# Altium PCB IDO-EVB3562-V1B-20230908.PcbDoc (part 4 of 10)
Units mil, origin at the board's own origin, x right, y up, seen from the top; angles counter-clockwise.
Board outline 5314.96 x 3543.31 mil, 4 copper layers (TOP, L2-VCC, L3-GND, BOTTOM), stack 28.8 mil thick; 747 components, 560 nets, 2514 pads, 1964 vias.
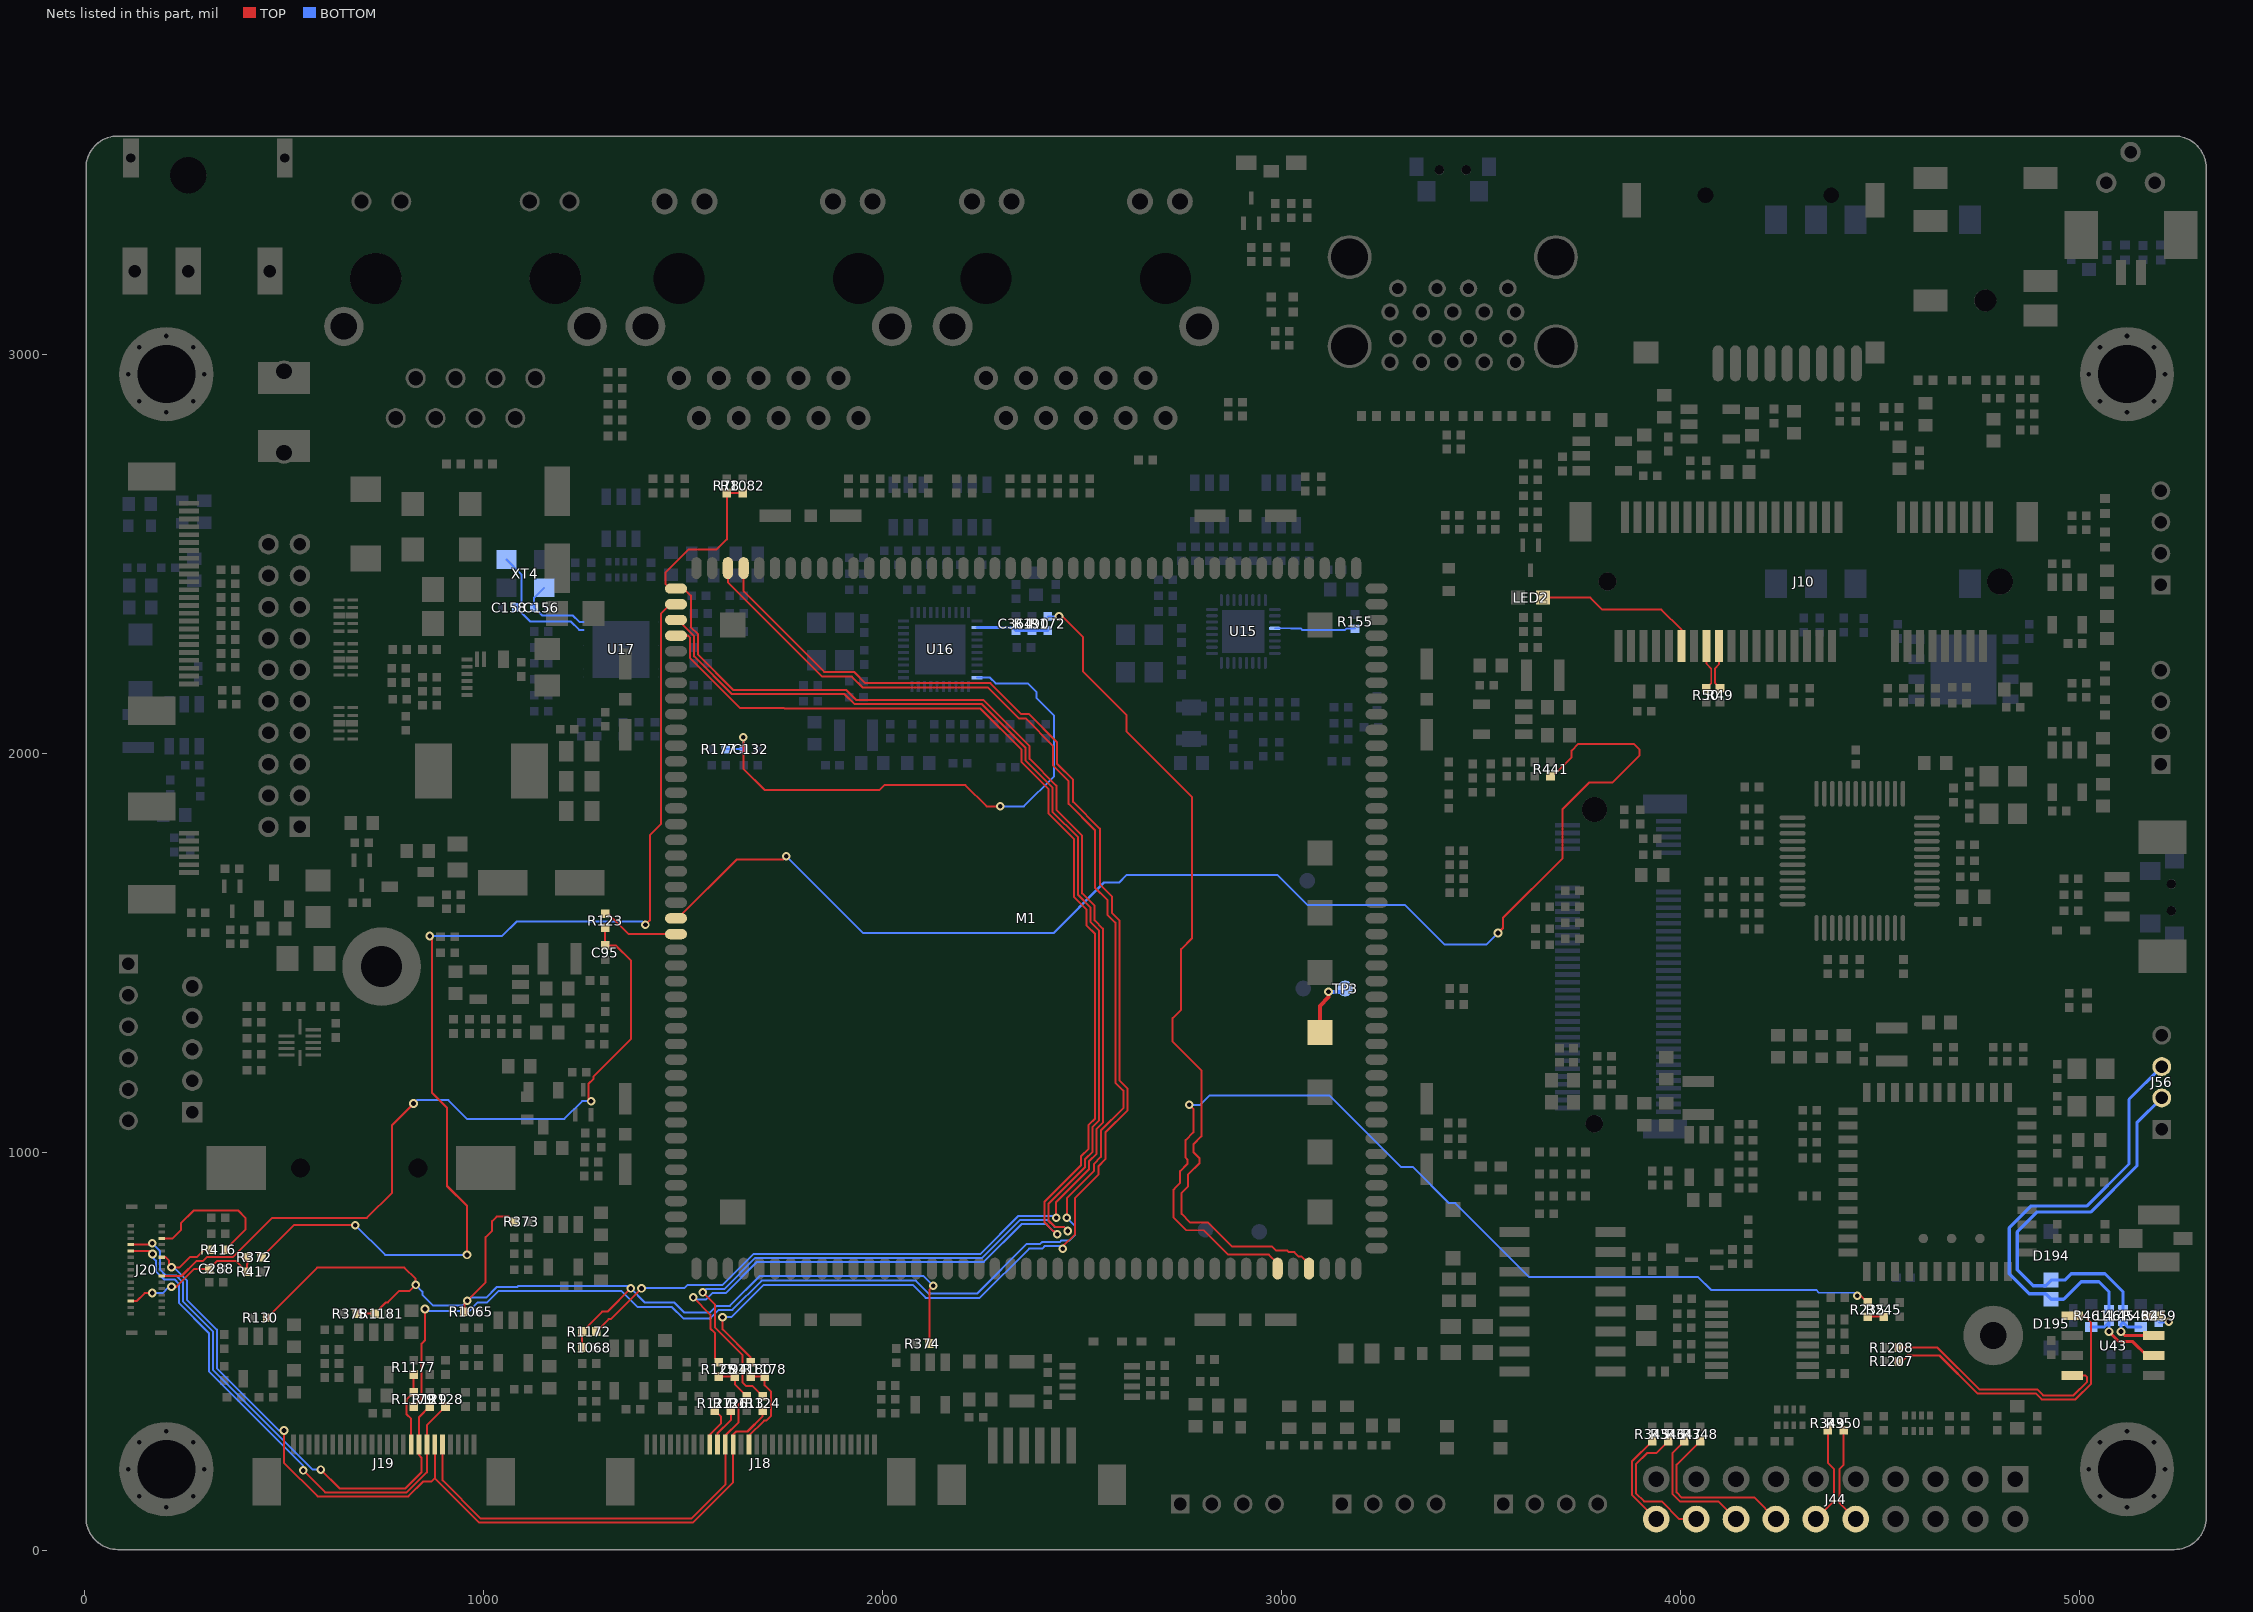
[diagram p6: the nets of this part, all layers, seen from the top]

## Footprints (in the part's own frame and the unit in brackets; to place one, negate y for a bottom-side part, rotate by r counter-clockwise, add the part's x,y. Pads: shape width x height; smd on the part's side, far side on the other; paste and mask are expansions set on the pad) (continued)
SILKSCREEN_TOP#14 [mm] "SILKSCREEN_TOP"
  rect 1.1x0.6 smd: 1(-1.35,0.95) 2(-1.35,0) 3(-1.35,-0.95) 4(1.35,-0.95) 5(1.35,0.95)
  silkscreen extent -2.03,-1.45 0.48,1.78, body extent -2.15,-1.8 2.15,1.65, height 3.81
SILKSCREEN_TOP#15 [mm] "SILKSCREEN_TOP"
  oct 0.025x0.025 smd: 1(-1.1,0.5) 2(0,-0.3) 3(-1.3,-1.1)
  rect 1.1x0.7 smd: 4(1.15,-1.02)
  rect 1x0.254 smd: 5(1.15,0.225) 6(1.15,0.675)
  rect 0.25x0.7 smd: 7(1.125,1.3) 8(0.675,1.3) 9(0.225,1.3) 10(-0.225,1.3) 11(-0.675,1.3) 12(-1.125,1.3)
  TOP region: 0.25,0.8 -1.55,0.8 -1.55,0.1 -0.8,0.1 -0.4,0.5 0.25,0.5 0.25,0.8
  TOP region: 0.25,0.8 -1.55,0.8 -1.55,0.1 -0.8,0.1 -0.4,0.5 0.25,0.5 0.25,0.8
  TOP region: 0.25,-1.4 -1.55,-1.4 -1.55,-0.7 -0.8,-0.7 -0.4,-1.1 0.25,-1.1 0.25,-1.4
  TOP region: 0.25,-1.4 -1.55,-1.4 -1.55,-0.7 -0.8,-0.7 -0.4,-1.1 0.25,-1.1 0.25,-1.4
  TOP region: -0.2,0.1 -0.5,-0.2 -0.5,-0.4 -0.2,-0.7 0.2,-0.7 0.5,-0.4 0.5,-0.2 0.2,0.1 -0.2,0.1
  TOP region: -0.2,0.1 -0.5,-0.2 -0.5,-0.4 -0.2,-0.7 0.2,-0.7 0.5,-0.4 0.5,-0.2 0.2,0.1 -0.2,0.1
  silkscreen extent -2.15,-1.5 1.5,1.5, body extent -1.55,-1.5 1.55,1.5, height 3.81
SILKSCREEN_TOP#16 [mm] "SILKSCREEN_TOP"
  rect 1.2x1.3 smd: 1(-0.9,1.2) 2(-0.9,-1.2) 3(0.9,-1.2) 4(0.9,1.2)
  silkscreen extent -1.92,-1.6 1.25,1.6, body extent -1.5,-1.85 1.5,1.85, height 3.81

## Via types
v1: diameter 21.65, hole 11.81, TOP to BOTTOM, 1964 vias

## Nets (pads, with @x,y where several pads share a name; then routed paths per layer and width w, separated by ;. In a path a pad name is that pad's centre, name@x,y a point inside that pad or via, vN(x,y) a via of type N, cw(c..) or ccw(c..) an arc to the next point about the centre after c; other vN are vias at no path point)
4G_DM: J10.36 R49.2 | length 115.2
  TOP w4.5: J10.36@4097.4,2268.6 4097.4,2222.67 4087.4,2212.67 4087.4,2175.32 R49.2@4100,2162.72
4G_DP: J10.38 R50.2 | length 116.2
  TOP w4.5: R50.2@4065,2162.72 4077.9,2175.62 4077.9,2212.1 4065.9,2224.1 J10.38@4065.9,2268.6
4G_LED_WANN#: J10.42 LED2.C | length 421
  TOP w5: LED2.C@3656.5,2390 3775,2390 3805,2360 3953,2360 4002.9,2310.1 J10.42@4002.9,2268.6
4G_POWER_H: M1.108 R441.1 | length 3262.6
  TOP w5: M1.108@1482.87,1585.83 1487.06,1585.83 1634.58,1733.35 1750.89,1733.35 v1(1759.22,1741.67) ; v1(3543.47,1549.33) 3555.81,1561.67 3555.81,1587.06 3704.43,1735.67 3704.43,1858.74 3772.69,1927 3830.75,1927 3897.61,1993.86 3897.61,2009.26 3883.54,2023.33 3744.95,2023.33 3728,2006.38 3728,1989.62 3680.66,1942.28 R441.1@3675,1942.28
  BOTTOM w5: v1(1759.22,1741.67) 1951.93,1548.96 2428.96,1548.96 2555.69,1675.69 2593.58,1675.69 2612.89,1695 2990,1695 3066,1619 3310.64,1619 3409.69,1519.94 3514.08,1519.94 v1(3543.47,1549.33)
ADC0: J44.10 R350.2 | length 243.8
  TOP w5: R350.2@4410,302.28 4410,216 4399,205 4399,121 J44.10@4440,80
ADC1: J44.12 R349.2 | length 247.1
  TOP w5: J44.12@4340,80 4385,125 4385,206 4370,221 R349.2@4370,302.28
ADC2: J44.14 R348.2 | length 429.7
  TOP w5: R348.2@4050,275.28 3990.97,216.25 3990.97,146.72 4004.14,133.54 4186.46,133.54 J44.14@4240,80
ADC3: J44.16 R347.2 | length 329.7
  TOP w5: R347.2@4010,275.28 3980.97,246.25 3980.97,142.57 4000,123.54 4096.46,123.54 J44.16@4140,80
ADC4: J44.18 R346.2 | length 355
  TOP w5: R346.2@3970,275.28 3939.72,245 3916.86,245 3889.03,217.17 3889.03,145.11 3909.57,124.57 3953.36,124.57 3997.93,80 J44.18@4040,80
ADC5: J44.20 R345.2 | length 241.6
  TOP w5: R345.2@3930,275.28 3879.03,224.31 3879.03,140.97 J44.20@3940,80
AF-PWDN: J20.26 R416.2 | length 356.8
  TOP w5: J20.26@193.98,783.74 220.66,783.74 241.33,804.41 241.33,821.33 273.5,853.5 384.83,853.5 403.33,835 403.33,805.61 R416.2@352.72,755
BATDIV: M1.176 TP3.1 | length 155.9
  TOP w10: M1.176@3096.65,1300 3096.65,1366.65 3118.29,1388.3 v1(3118.29,1401.8)
  BOTTOM w10: v1(3118.29,1401.8) 3151.8,1401.8 TP3.1@3160,1410
BT_REG_ON_H: R235.2 R245.1 | length 40
  TOP w5: R235.2@4470,587.28 R245.1@4510,587.28
BT_REG_ON_H_GPIO0_B0_D: M1.167 R235.1 | length 2559.2
  TOP w5: v1(2769,1118.59) 2779.55,1108.04 2779.55,1049.55 2760,1030 2760,985.86 2765,980.86 2765,970.71 2746.68,952.39 2746.68,922.67 2735.88,911.87 2730.03,906.02 2730.03,835.83 2761.86,804 2806,804 2867.07,742.93 2969.07,742.93 2990.75,721.25 M1.167@2990.75,707.87 ; v1(4444.12,640.12) 4452.6,640.12 R235.1@4470,622.72
  BOTTOM w5: v1(2769,1118.59) 2797.01,1118.59 2820.49,1142.07 3120.79,1142.07 3299.86,963 3329.58,963 3420.41,872.17 3436.58,872.17 3622.08,686.67 4044.91,686.67 4077.23,654.35 4340.65,654.35 4347.67,647.33 4436.91,647.33 v1(4444.12,640.12)
CAM_CLK0_OUT_M1: M1.109 R123.1 | length 199.2
  TOP w5: R123.1@1305,1597.72 1313.28,1597.72 1364.65,1546.35 1425.35,1546.35 1425.46,1546.46 M1.109@1482.87,1546.46
CAM_CLK2_OUT: M1.84 R1179.1 | length 4437
  TOP w5: R1179.1@825,362.28 845,382.28 845,520 853.53,528.53 v1(853.53,606.52) ; M1.84@1612.8,2463.78 1612.8,2428.2 1849,2192 1923.73,2192 1951.41,2164.33 2265.1,2164.33 2342.43,2087 2358.92,2087 2428.33,2017.59 2428.33,1993.59 ; 2428.32,1993.58 2428.32,1985.3 2428.32,1968.73 2467,1930.05 2467,1873 2533,1807 2533,1663 2564,1632 2564,1595 2584,1575 2584,1174 2604,1154 2604,1110 2548,1054 2548,988 2530,970 2530,952 2462.42,884.42 v1(2462.42,835)
  BOTTOM w5: v1(853.53,606.52) 859.05,601 964,601 986,623 1009,623 1037.5,651.5 1346.5,651.5 1386.66,611.34 1472.66,611.34 1501,583 1569,583 1590.33,604.33 1623.88,604.33 1697.45,677.9 2084.1,677.9 2116.7,645.3 2237.3,645.3 2361.7,769.7 2395.7,769.7 2400.58,774.58 2444.75,774.58 2448.17,778 2468,778 2483.17,793.17 2483.17,814.25 v1(2462.42,835)
CAM_CLK3_OUT: M1.83 R1180.1 | length 3509.9
  TOP w5: v1(1599.36,586) 1599.36,555.7 1670,485.06 R1180.1@1670,472.72 ; M1.83@1652.16,2463.78 1652.16,2405.84 1854,2204 1928.88,2204 1957.55,2175.33 2270.67,2175.33 2347.39,2098.61 2366.45,2098.61 2438.33,2026.74 2438.33,1989.44 ; 2438.32,1989.44 2438.32,1981.16 2438.32,1972.88 2478,1933.2 2478,1878 2545,1811 2545,1671 2576,1640 2576,1599 2594,1581 2594,1180 2615,1159 2615,1105 2559,1049 2559,982 2542,965 2542,944 2483.17,885.17 2483.17,794.43 2452.2,763.47 v1(2452.2,757.84)
  BOTTOM w5: v1(1599.36,586) 1621.69,586 1702.69,667 2076,667 2108.7,634.3 2244.04,634.3 2367.74,758 2401,758 2407.58,764.58 2445.46,764.58 v1(2452.2,757.84)
CAN0_H: D194.A J56.2 L45.2 | length 1015.5
  BOTTOM w8: L45.2@5110,606.93 5110,650 5065,695 4980,695 4963.98,678.98 D194.A@4930,678.98 4916.02,665 4885,665 4845,705 4845,800 4895,850 5030,850 5145,965 5145,1073.35 J56.2@5207.28,1135.63
CAN0_L: D195.A J56.3 L46.2 | length 1107.9
  BOTTOM w8: L46.2@5075,606.93 5075,650 5050,675 5005,675 4961.02,631.02 D195.A@4930,631.02 4916.02,645 4875,645 4825,695 4825,810 4880,865 5020,865 5125,970 5125,1132.09 J56.3@5207.28,1214.37
CAN0_RX_M2: R1208.2 U43.4 | length 586.5
  TOP w5: R1208.2@4547.72,510 4645,510 4750,405 4895,405 4910,390 4986,390 5020,424 5020,435 5015,440 U43.4@4982.64,440
CAN0_STB_IO: R459.1 U43.8 | length 70
  TOP w5: U43.8@5187.36,590 5210,590 v1(5225,575)
  BOTTOM w5: R459.1@5200,572.28 5222.28,572.28 v1(5225,575)
CAN0_TX_M2: R1207.2 U43.1 | length 758
  TOP w5: R1207.2@4547.72,475 4555,475 4570,490 4650,490 4745,395 4890.86,395 4905.86,380 4991,380 5030,419 5030,572 5012,590 U43.1@4982.64,590
CAN0H: L45.1 R462.1 U43.7 | length 161.5
  TOP w8: v1(5105,550) 5115,540 U43.7@5187.36,540
  BOTTOM w8: v1(5105,550) 5105,568.07 L45.1@5110,573.07 5121.61,561.46 R462.1@5155,561.46
CAN0L: L46.1 R461.1 U43.6 | length 210.1
  TOP w8: v1(5075,550) 5100,525 5135,525 5170,490 U43.6@5187.36,490
  BOTTOM w8: R461.1@5030,561.46 5063.39,561.46 L46.1@5075,573.07 v1(5075,550)
CIF1_SCL: J18.21 R126.2 | length 99.1
  TOP w5: J18.21@1586.73,267.01 1586.73,295 1620,328.27 R126.2@1620,352.28
CIF1_SDA: J18.22 R127.2 | length 103.1
  TOP w5: J18.22@1567.05,267.01 1567.05,291.05 1595,319 1595,337.28 R127.2@1580,352.28
CIF2_RST: C288.2 J20.5 R372.2 R417.1 | length 380.3
  TOP w5: J20.5@116.03,626.26 130.26,626.26 150.59,646.59 v1(169.9,646.59) ; v1(218.07,662.25) 230.25,662.25 275,707 C288.2@312.28,707 331.93,726.65 380.63,726.65 R417.1@407.28,700 407.28,719 408.28,720 R372.2@408.28,736
  BOTTOM w5: v1(169.9,646.59) 195.65,646.59 211.31,662.25 v1(218.07,662.25)
CIF2_RST_L: M1.88 R372.1 | length 2820.4
  TOP w5: R372.1@443.72,736 524.55,816.83 v1(678.75,816.83) ; v1(865.6,1541.78) 870.61,1536.77 870.61,1149.39 908.65,1111.35 908.65,915 958.75,864.9 v1(958.75,742.17) ; v1(1406,1569.67) 1417,1580.67 1417,1793.92 1445,1821.92 1445,2350 1468.23,2373.23 M1.88@1482.87,2373.23
  BOTTOM w5: v1(678.75,816.83) 753.4,742.17 v1(958.75,742.17) ; v1(865.6,1541.78) 1046.78,1541.78 1083,1578 1397.67,1578 v1(1406,1569.67)
CIF2_SCL: J19.7 J20.21 R128.2 | length 1310.1
  TOP w5: J20.21@116.03,752.24 162.61,752.24 v1(170.34,744.51) ; v1(548.02,202) 603.35,146.67 807.74,146.67 858.27,197.2 J19.7@858.27,267.01 858.27,315.55 R128.2@905,362.28
  BOTTOM w5: v1(170.34,744.51) 170.34,735.89 178.67,727.56 178.67,701.76 199.86,680.58 225.66,680.58 236.39,669.84 236.39,621.75 311.67,546.48 311.67,450.12 548.02,213.77 v1(548.02,202)
CIF2_SDA: J19.8 J20.23 R129.2 | length 1291.3
  TOP w5: J20.23@116.03,767.99 166.55,767.99 v1(169.72,771.15) ; v1(592,204) 639.33,156.67 803.59,156.67 844.77,197.85 844.77,234.23 838.58,240.42 J19.8@838.58,267.01 838.58,335.86 R129.2@865,362.28
  BOTTOM w5: v1(169.72,771.15) 188.67,752.2 188.67,705.9 204,690.58 229.8,690.58 246.39,673.98 246.39,625.9 321.67,550.62 321.67,454.26 571.94,204 v1(592,204)
CIF_EN: R130.1 R373.1 R374.1 R375.1 R1065.1 R1068.1 R1172.2 R1181.1 | length 2725.1
  TOP w5: R130.1@457.72,585 457.72,585.14 583.08,710.5 801.5,710.5 830,682 v1(830,667.02) 814.98,652 789,652 760.5,623.5 755.78,623.5 R1181.1@727.28,595 R375.1@682.72,595 ; R1065.1@952.28,600 952.28,619.77 v1(959.53,627.02) 1005.67,673.16 1005.67,786.53 1022,802.85 1022,827 1033,838 1064.28,838 R373.1@1077.28,825 ; R1068.1@1247.28,510 R1172.2@1247.28,550 1297.28,600 1310.98,600 v1(1369.15,658.17) ; R374.1@2117.72,520 2117.72,654.89 v1(2127.46,664.63)
  BOTTOM w5: v1(830,667.02) 846.67,650.35 846.67,642.41 874.08,615 947.51,615 v1(959.53,627.02) 967.86,635.35 1006.55,635.35 1032.71,661.5 1084.63,661.5 1087.13,664 1363.32,664 v1(1369.15,658.17) 1404.98,622.34 1479,622.34 1504.02,597.32 1567.32,597.32 1584.33,614.33 1617.73,614.33 1693.31,689.9 2102.18,689.9 v1(2127.46,664.63)
CIF_PDN: J18.19 J19.6 J20.20 R124.2 R416.1 | length 2355.5
  TOP w5: J20.20@193.98,736.49 203.51,736.49 212,728 212,717.1 v1(217.99,711.11) 238.64,711.11 264.02,736.49 281.49,736.49 300,755 R416.1@317.28,755 ; v1(499.93,301.93) 499.93,221.07 584.33,136.67 811.88,136.67 849.75,174.54 870,174.54 877.95,182.49 ; J19.6@877.95,267.01 877.95,182.49 ; R124.2@1700,352.28 1700,337.6 1661.91,299.51 1633.51,299.51 1626.1,292.1 J18.19@1626.1,267.01 1626.1,171.96 1525.15,71 989.44,71 877.95,182.49
  BOTTOM w5: v1(217.99,711.11) 223.41,711.11 256.39,678.13 256.39,630.04 331.67,554.76 331.67,458.41 488.15,301.93 v1(499.93,301.93)
CIF_PDN_L: M1.89 R124.1 | length 3744.4
  TOP w5: M1.89@1482.87,2333.86 1487.61,2333.86 1527.93,2293.53 1527.93,2242.53 1622.13,2148.33 1904.84,2148.33 1929.84,2123.33 2248.53,2123.33 2359,2012.86 2359,1981.48 2426,1914.48 2426,1853.46 2490.74,1788.71 2490.74,1644.48 2522.35,1612.88 2522.35,1576.65 2543,1556 2543,1079 2527,1063 2527,1001 2508,982 2508,962 2416.53,870.53 2416.53,828.47 2432.76,812.24 2454.62,812.24 v1(2464.84,802.02) ; v1(1549.83,648.17) 1580,618 1580,560.92 1650,490.92 1650,422 1659,413 1674.72,413 R124.1@1700,387.72
  BOTTOM w5: v1(1549.83,648.17) 1558.15,656.5 1603.33,656.5 1681.67,734.83 2250.3,734.83 2344.7,829.22 2415.28,829.22 2431.91,812.59 2454.27,812.59 v1(2464.84,802.02)
CIF_PWREN_H: M1.87 R78.2 R1082.2 R1172.1 | length 4112.4
  TOP w5: R1172.1@1282.72,550 1313.72,581 1319.17,581 v1(1396.35,658.17) ; R1082.2@1650,2652.28 R78.2@1610,2652.28 1610,2536 1584,2510 1513.75,2510 1456,2452.25 1456,2425 1468.4,2412.6 M1.87@1482.87,2412.6 1502.4,2412.6 1520,2395 1520,2315.61 1537.93,2297.68 1537.93,2246.67 1626.28,2158.33 1908.98,2158.33 1933.98,2133.33 2252.67,2133.33 2369,2017 2369,1985.62 2436,1918.62 2436,1857.6 2500.74,1792.86 2500.74,1648.63 2532.35,1617.02 2532.35,1580.8 2553,1560.14 2553,1074 2537,1058 2537,996 2518,977 2518,957 2435.76,874.76 v1(2435.76,835.15)
  BOTTOM w5: v1(1396.35,658.17) 1398.02,659.85 1504.35,659.85 1511,666.5 1599.19,666.5 1677.52,744.83 2246.16,744.83 2341.33,840 2430.92,840 v1(2435.76,835.15)
CIF_RST: C94.2 J18.20 J19.5 R113.1 R125.2 | length 1219.4
  TOP w5: J19.5@897.64,267.01 897.64,176.95 993.58,81 1521,81 1606.42,166.42 J18.20@1606.42,267.01 1606.42,289.42 1640,323 1640,367.72 R113.1@1660,387.72 1630.01,417.71 C94.2@1630.01,437.28 R125.2@1590,437.28
CIF_RST_L: M1.90 R125.1 | length 3564.8
  TOP w5: M1.90@1482.87,2294.49 1512.84,2294.49 1517.93,2289.39 1517.93,2238.38 1642.99,2113.33 1753.29,2113.33 1754.94,2111.67 2246.04,2111.67 2349,2008.71 2349,1977.34 2416,1910.34 2416,1849.32 2480.74,1784.57 2480.74,1639.26 2512.35,1607.65 2512.35,1567.65 2533,1547 2533,1084 2517,1068 2517,1008 2498,989 2498,967 2406.53,875.53 2406.53,823.83 2428.34,802.02 2430.06,802.02 v1(2438.17,793.91) ; v1(1526.03,635.65) 1569,592.68 1569,557.78 1580,546.78 1580,482.72 R125.1@1590,472.72
  BOTTOM w5: v1(1526.03,635.65) 1531.83,629.85 1557.42,629.85 1574.07,646.5 1607.48,646.5 1685.81,724.83 2254.45,724.83 2348.84,819.22 2411.14,819.22 2428.34,802.02 2430.06,802.02 v1(2438.17,793.91)
CKXTALIN: C156.1 U17.32 XT4.3 | length 198.1
  BOTTOM w5: XT4.3@1152.24,2414.57 1127.28,2389.6 C156.1@1127.28,2365 1147.28,2345 1224.34,2345 1240.39,2328.95 U17.32@1250.5,2328.95
CKXTALOUT: C158.2 U17.31 XT4.1 | length 331.8
  BOTTOM w5: XT4.1@1057.76,2485.43 1095,2448.19 1095,2377.28 C158.2@1082.72,2365 1117.72,2330 1219.34,2330 1240.09,2309.25 U17.31@1250.5,2309.25
CLKREQB: R155.2 U15.12 | length 204
  BOTTOM w4: U15.12@2983.74,2312.87 3024,2312.87
  BOTTOM w5: 3024,2312.87 3048.5,2312.87 3052.12,2309.25 3160.25,2309.25 3163.28,2312.28 R155.2@3185,2312.28
CSI0_MCLK: C95.2 J20.14 R123.2 | length 1920
  TOP w5: J20.14@193.98,689.25 243.11,689.25 280.35,726.49 296.49,726.49 306.65,736.65 371.65,736.65 470.15,835.15 707.84,835.15 771.02,898.34 771.02,1067.85 v1(824.84,1121.67) ; v1(1269.88,1127.62) 1263.41,1134.1 1263.41,1170.73 1276.07,1183.39 1276.07,1189.83 1370,1283.75 1370,1480 1332.28,1517.72 C95.2@1304.99,1517.72 ; C95.2@1304.99,1517.72 R123.2@1305,1562.28
  BOTTOM w5: v1(824.84,1121.67) 833.16,1130 911.86,1130 958.71,1083.14 1202.67,1083.14 1247.14,1127.62 v1(1269.88,1127.62)
CSI2_MCLK: J19.9 R1177.1 R1179.2 | length 187.9
  TOP w5: J19.9@818.9,267.01 818.9,331.1 806.65,343.35 806.65,379.37 R1179.2@825,397.72 R1177.1@825,442.28
CSI3_MCLK: J18.17 R1178.1 R1180.2 | length 238.3
  TOP w5: J18.17@1665.47,267.01 1665.47,288.93 1703.54,327 1709.42,327 1721,338.58 1721,399.03 1705,415.03 R1178.1@1705,437.28 R1180.2@1670,437.28
GMAC0_TXCLK_: C132.2 R177.2 U16.20 | length 1406.3
  TOP w5: v1(1651.52,2040) 1651.52,1960.91 1704.6,1907.83 1993.08,1907.83 2005.25,1920 2207.95,1920 2261.25,1866.7 v1(2295.26,1866.7)
  BOTTOM w5: R177.2@1607.72,2010 C132.2@1652.28,2010 1652.28,2039.24 v1(1651.52,2040) ; U16.20@2237.52,2189.13 2269.87,2189.13 2284,2175 2364.86,2175 2385.97,2153.89 2385.97,2138.56 2430.5,2094.03 2430.5,1942.5 2354.7,1866.7 v1(2295.26,1866.7)
GMAC1_RSTN: C364.2 R172.2 R190.1 U16.12 | length 180.7
  BOTTOM w8: U16.12@2237.52,2315.12 2327.16,2315.12 C364.2@2335,2307.28 R190.1@2375,2307.28 R172.2@2415,2307.28
GMAC1_RSTN_GPIO0_A6_D: M1.169 R172.1 | length 2134.9
  TOP w5: v1(2442.7,2342.72) 2451.24,2342.72 2503.35,2290.62 2503.35,2204.36 2611.65,2096.05 2611.65,2054.96 2776.65,1889.96 2776.65,1536.65 2748.8,1508.8 2748.8,1356.72 2727.67,1335.59 2727.67,1276.89 2799.55,1205.01 2799.55,1039.55 2780,1020 2780,1000 2795,985 2795,972.43 2766.68,944.11 2766.68,914.38 2750.03,897.73 2750.03,844.97 2771,824 2816,824 2877.07,762.93 2977.35,762.93 2987.35,752.93 3015.07,752.93 3019,749 3033,749 3044,738 3051,738 3069.49,719.51 M1.169@3069.49,707.87
  BOTTOM w5: R172.1@2415,2342.72 v1(2442.7,2342.72)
